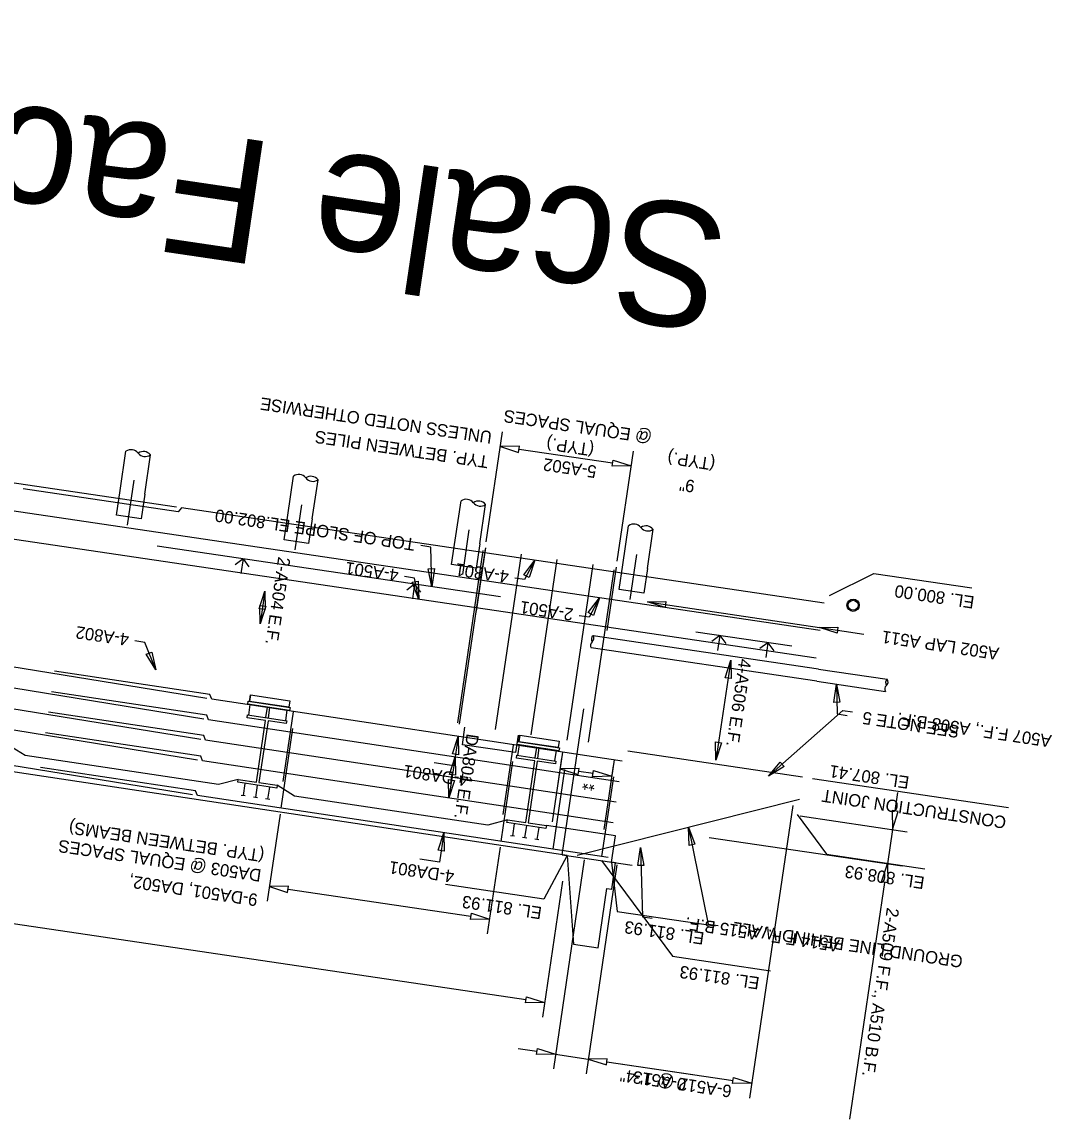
# Model space of a CAD drawing. Extents: x 1468952 to 1469875, y 573916 to 574139.
# Drawn here: x 1469049.93 to 1469091.48, y 574051.68 to 574095.95 of the extents above; entities that cross this region are included whole.
import ezdxf

# ---------------------------------------------------------------- set-up
doc = ezdxf.new("R2010")
doc.units = 0
for name, color, linetype in [('BR_P_Beam_Object', 7, 'Continuous'), ('BR_P_Beam_Stl_Det', 7, 'Continuous'), ('BR_P_Gen_Centerline', 7, 'Continuous'), ('BR_P_Gen_Phase_Construction', 7, 'Continuous'), ('BR_P_Sub_Centerline', 7, 'Continuous'), ('BR_P_Sub_Deep_Centerline', 7, 'Continuous'), ('BR_P_Sub_Foot_Centerline', 7, 'Continuous'), ('BR_P_Sub_Text', 7, 'Continuous'), ('BR_X_SV_Beam_Seat', 7, 'Continuous'), ('Default', 7, 'Continuous'), ('GE_P_CL_50', 7, 'Continuous'), ('GK_Cells', 7, 'Continuous'), ('PF_X_Ground_Line', 7, 'Continuous'), ('PV_X_EOP', 7, 'Continuous'), ('SV_X_Text_Elevation', 7, 'Continuous'), ('UT_X_Water', 7, 'Continuous')]:
    doc.layers.add(name, color=color, linetype=linetype)

# ---------------------------------------------------------------- blocks, each defined once
blk = doc.blocks.new('arrowOhio')
at = {"layer": 'Default'}
blk.add_lwpolyline([(0.00381, 0.000635), (0.00381, -0.000635), (0, 0)], close=True, dxfattribs=at)

msp = doc.modelspace()

# ---------------------------------------------------------------- linework, layer by layer
at = {"layer": 'BR_P_Beam_Object'}
for p, q in [((1469082.065, 574069.842), (1469072.965, 574071.189)), ((1469081.992, 574069.347), (1469072.891, 574070.694)), ((1469072.33, 574062.337), (1469081.288, 574064.593))]:
    msp.add_line(p, q, dxfattribs=at)
for centre, start, end in [((1469073.04, 574070.799), 127.976, 215.1816), ((1469073.076, 574071.046), 127.976, 215.1816), ((1469072.817, 574071.085), 307.976, 35.1816)]:
    msp.add_arc(centre, 0.181, start, end, dxfattribs=at)
at = {"layer": 'BR_P_Beam_Stl_Det'}
for p, q in [((1469068.524, 574074.626), (1469067.494, 574067.667)), ((1469068.619, 574074.697), (1469067.57, 574067.614)), ((1469068.625, 574074.738), (1469068.247, 574072.182)), ((1469070.063, 574074.483), (1469069.014, 574067.4)), ((1469071.507, 574074.269), (1469070.458, 574067.186)), ((1469072.951, 574074.055), (1469071.903, 574066.972)), ((1469073.901, 574073.957), (1469073.522, 574071.401)), ((1469073.8, 574073.845), (1469072.77, 574066.886))]:
    msp.add_line(p, q, dxfattribs=at)
for points in [[(1469056.161, 574076.372), (1469030.427, 574080.182), (1469030.303, 574080.026), (1469024.038, 574080.953)], [(1469082.126, 574071.391), (1469046.506, 574076.665), (1469046.433, 574076.85), (1469043.3, 574077.314)], [(1469082.291, 574072.504), (1469056.359, 574076.343), (1469056.235, 574076.186), (1469049.97, 574077.114)], [(1469081.962, 574070.278), (1469046.341, 574075.552), (1469046.268, 574075.738), (1469043.135, 574076.201)]]:
    msp.add_lwpolyline(points, dxfattribs=at)
at = {"layer": 'BR_P_Gen_Centerline'}
for p, q in [((1469082.065, 574069.842), (1469084.835, 574069.432)), ((1469081.992, 574069.347), (1469084.762, 574068.937))]:
    msp.add_line(p, q, dxfattribs=at)
for radius in [0.25, 0.2]:
    msp.add_circle((1469083.457, 574072.416), radius, dxfattribs=at)
for centre, start, end in [((1469084.91, 574069.041), 127.976, 215.1816), ((1469084.947, 574069.289), 127.976, 215.1816), ((1469084.687, 574069.327), 307.976, 35.1816)]:
    msp.add_arc(centre, 0.181, start, end, dxfattribs=at)
at = {"layer": 'BR_P_Gen_Phase_Construction'}
for p, q in [((1469053.887, 574077.046), (1469054.122, 574078.629)), ((1469054.877, 574076.9), (1469055.111, 574078.482)), ((1469060.647, 574076.045), (1469060.881, 574077.628)), ((1469061.636, 574075.899), (1469061.871, 574077.482)), ((1469067.407, 574075.045), (1469067.641, 574076.627)), ((1469068.396, 574074.898), (1469068.63, 574076.481)), ((1469074.166, 574074.044), (1469074.401, 574075.627)), ((1469075.155, 574073.897), (1469075.39, 574075.48))]:
    msp.add_line(p, q, dxfattribs=at)
for centre, start, end in [((1469054.331, 574078.332), 37.976, 125.1816), ((1469054.825, 574078.259), 37.976, 125.1816), ((1469054.902, 574078.779), 217.976, 305.1816), ((1469061.09, 574077.332), 37.976, 125.1816), ((1469061.585, 574077.258), 37.976, 125.1816), ((1469061.662, 574077.778), 217.976, 305.1816), ((1469067.85, 574076.331), 37.976, 125.1816), ((1469068.344, 574076.258), 37.976, 125.1816), ((1469068.421, 574076.777), 217.976, 305.1816), ((1469074.609, 574075.33), 37.976, 125.1816), ((1469075.104, 574075.257), 37.976, 125.1816), ((1469075.181, 574075.776), 217.976, 305.1816)]:
    msp.add_arc(centre, 0.362, start, end, dxfattribs=at)
at = {"layer": 'BR_P_Sub_Centerline'}
for p, q in [((1469053.741, 574076.057), (1469053.887, 574077.046)), ((1469054.877, 574076.9), (1469054.73, 574075.91)), ((1469054.73, 574075.91), (1469053.741, 574076.057)), ((1469060.501, 574075.056), (1469060.647, 574076.045)), ((1469061.636, 574075.899), (1469061.49, 574074.91)), ((1469061.49, 574074.91), (1469060.501, 574075.056)), ((1469067.26, 574074.055), (1469067.407, 574075.045)), ((1469068.396, 574074.898), (1469068.249, 574073.909)), ((1469068.249, 574073.909), (1469067.26, 574074.055)), ((1469074.02, 574073.055), (1469074.166, 574074.044)), ((1469075.155, 574073.897), (1469075.009, 574072.908)), ((1469075.009, 574072.908), (1469074.02, 574073.055))]:
    msp.add_line(p, q, dxfattribs=at)
at = {"layer": 'BR_P_Sub_Deep_Centerline'}
for q in [(1469072.594, 574068.231), (1469074.541, 574061.928)]:
    msp.add_line((1469071.723, 574062.345), q, dxfattribs=at)
at = {"layer": 'BR_P_Sub_Foot_Centerline'}
for p, q in [((1469059.073, 574067.986), (1469059.136, 574068.409)), ((1469059.77, 574067.883), (1469059.833, 574068.306)), ((1469059.869, 574067.868), (1469059.932, 574068.291)), ((1469060.566, 574067.765), (1469060.629, 574068.188)), ((1469069.936, 574066.358), (1469069.998, 574066.78)), ((1469070.633, 574066.255), (1469070.695, 574066.677)), ((1469070.732, 574066.24), (1469070.794, 574066.663)), ((1469071.429, 574066.137), (1469071.491, 574066.559))]:
    msp.add_line(p, q, dxfattribs=at)
at = {"layer": 'BR_P_Sub_Text'}
for p, q in [((1469057.382, 574068.654), (1469035.698, 574072.185)), ((1469057.26, 574067.826), (1469035.575, 574071.358)), ((1469057.137, 574066.999), (1469035.453, 574070.53)), ((1469057.015, 574066.171), (1469035.33, 574069.703)), ((1469057.506, 574068.81), (1469051.244, 574069.755)), ((1469057.384, 574067.983), (1469051.121, 574068.928)), ((1469057.58, 574068.624), (1469057.506, 574068.81)), ((1469074.146, 574066.124), (1469057.58, 574068.624)), ((1469056.807, 574064.767), (1469035.123, 574068.299)), ((1469057.261, 574067.155), (1469050.999, 574068.1)), ((1469057.457, 574067.797), (1469057.384, 574067.983)), ((1469074.023, 574065.297), (1469057.457, 574067.797)), ((1469060.87, 574068.11), (1469060.455, 574065.302)), ((1469057.139, 574066.328), (1469050.876, 574067.273)), ((1469060.38, 574064.229), (1469060.856, 574067.444)), ((1469057.335, 574066.969), (1469057.261, 574067.155)), ((1469073.901, 574064.469), (1469057.335, 574066.969)), ((1469069.744, 574066.776), (1469069.329, 574063.968)), ((1469071.733, 574066.482), (1469071.317, 574063.674)), ((1469057.212, 574066.142), (1469057.139, 574066.328)), ((1469073.778, 574063.642), (1469057.212, 574066.142)), ((1469069.253, 574062.89), (1469069.729, 574066.105)), ((1469073.817, 574066.181), (1469073.402, 574063.373)), ((1469056.931, 574064.924), (1469050.669, 574065.869)), ((1469071.356, 574062.572), (1469071.832, 574065.787)), ((1469073.323, 574062.275), (1469073.799, 574065.49)), ((1469057.005, 574064.738), (1469056.931, 574064.924)), ((1469073.571, 574062.238), (1469057.005, 574064.738))]:
    msp.add_line(p, q, dxfattribs=at)
at = {"layer": 'BR_X_SV_Beam_Seat'}
for p, q in [((1469069.23, 574072.753), (1469055.381, 574074.803)), ((1469058.844, 574074.29), (1469058.522, 574074.052)), ((1469058.844, 574074.29), (1469058.756, 574073.697)), ((1469058.844, 574074.29), (1469059.082, 574073.969)), ((1469065.768, 574073.265), (1469065.447, 574073.027)), ((1469065.768, 574073.265), (1469065.68, 574072.672)), ((1469065.768, 574073.265), (1469066.006, 574072.944)), ((1469080.988, 574070.759), (1469077.107, 574071.334)), ((1469078.078, 574071.19), (1469077.756, 574070.952)), ((1469078.078, 574071.19), (1469077.99, 574070.597)), ((1469078.078, 574071.19), (1469078.316, 574070.869)), ((1469080.018, 574070.903), (1469079.697, 574070.665)), ((1469080.018, 574070.903), (1469079.93, 574070.309)), ((1469080.018, 574070.903), (1469080.256, 574070.582)), ((1469081.815, 574065.421), (1469089.729, 574064.249))]:
    msp.add_line(p, q, dxfattribs=at)
msp.add_lwpolyline([(1469069.941, 574067.179), (1469069.836, 574066.468), (1469067.692, 574066.785), (1469067.798, 574067.496)], dxfattribs=at)
at = {"layer": 'GE_P_CL_50'}
for p, q in [((1469059.145, 574068.797), (1469059.107, 574068.539)), ((1469059.039, 574068.423), (1469059.057, 574068.547)), ((1469060.726, 574068.173), (1469059.039, 574068.423)), ((1469059.057, 574068.547), (1469060.744, 574068.297)), ((1469060.733, 574068.562), (1469060.694, 574068.304)), ((1469060.744, 574068.297), (1469060.726, 574068.173)), ((1469069.901, 574066.795), (1469069.92, 574066.918)), ((1469069.92, 574066.918), (1469071.606, 574066.669)), ((1469070.007, 574067.169), (1469069.969, 574066.911)), ((1469071.595, 574066.934), (1469071.557, 574066.676)), ((1469071.588, 574066.545), (1469069.901, 574066.795)), ((1469071.606, 574066.669), (1469071.588, 574066.545))]:
    msp.add_line(p, q, dxfattribs=at)
for points in [[(1469060.733, 574068.562), (1469060.694, 574068.304), (1469059.107, 574068.539), (1469059.145, 574068.797)], [(1469071.595, 574066.934), (1469071.557, 574066.676), (1469069.969, 574066.911), (1469070.007, 574067.169)]]:
    msp.add_lwpolyline(points, close=True, dxfattribs=at)
at = {"layer": 'GK_Cells'}
for p, q in [((1469059.015, 574067.879), (1469059.032, 574067.992)), ((1469059.753, 574067.77), (1469059.015, 574067.879)), ((1469059.032, 574067.992), (1469060.607, 574067.759)), ((1469059.384, 574065.276), (1469059.753, 574067.77)), ((1469059.853, 574067.755), (1469059.483, 574065.261)), ((1469060.591, 574067.646), (1469059.853, 574067.755)), ((1469060.607, 574067.759), (1469060.591, 574067.646)), ((1469069.878, 574066.251), (1469069.895, 574066.364)), ((1469070.616, 574066.141), (1469069.878, 574066.251)), ((1469069.895, 574066.364), (1469071.47, 574066.131)), ((1469070.247, 574063.648), (1469070.616, 574066.141)), ((1469070.715, 574066.127), (1469070.346, 574063.633)), ((1469071.453, 574066.018), (1469070.715, 574066.127)), ((1469071.47, 574066.131), (1469071.453, 574066.018)), ((1469058.629, 574065.272), (1469058.646, 574065.385)), ((1469060.205, 574065.039), (1469058.629, 574065.272)), ((1469058.646, 574065.385), (1469059.384, 574065.276)), ((1469058.922, 574065.229), (1469058.849, 574064.734)), ((1469059.417, 574065.155), (1469059.344, 574064.661)), ((1469059.483, 574065.261), (1469060.221, 574065.152)), ((1469059.912, 574065.082), (1469059.838, 574064.588)), ((1469060.221, 574065.152), (1469060.205, 574065.039)), ((1469058.932, 574064.722), (1469058.767, 574064.746)), ((1469059.426, 574064.649), (1469059.261, 574064.673)), ((1469059.921, 574064.575), (1469059.756, 574064.6)), ((1469069.492, 574063.644), (1469069.509, 574063.757)), ((1469069.509, 574063.757), (1469070.247, 574063.648)), ((1469071.067, 574063.411), (1469069.492, 574063.644)), ((1469069.785, 574063.6), (1469069.712, 574063.106)), ((1469070.279, 574063.527), (1469070.206, 574063.033)), ((1469070.346, 574063.633), (1469071.084, 574063.524)), ((1469070.774, 574063.454), (1469070.701, 574062.959)), ((1469071.084, 574063.524), (1469071.067, 574063.411)), ((1469069.794, 574063.094), (1469069.629, 574063.118)), ((1469070.289, 574063.02), (1469070.124, 574063.045)), ((1469070.783, 574062.947), (1469070.618, 574062.972))]:
    msp.add_line(p, q, dxfattribs=at)
at = {"layer": 'PF_X_Ground_Line'}
for p, q in [((1469071.925, 574062.316), (1469040.98, 574066.988)), ((1469073.868, 574063.112), (1469071.084, 574063.524)), ((1469073.711, 574062.048), (1469073.868, 574063.112)), ((1469071.925, 574062.316), (1469072.173, 574058.741)), ((1469071.925, 574062.316), (1469071.925, 574062.316)), ((1469071.925, 574062.316), (1469071.925, 574062.316)), ((1469073.876, 574062.027), (1469073.711, 574062.051)), ((1469073.718, 574060.955), (1469073.876, 574062.027)), ((1469073.165, 574058.594), (1469073.519, 574060.984)), ((1469073.519, 574060.984), (1469073.718, 574060.955)), ((1469072.173, 574058.741), (1469073.165, 574058.594))]:
    msp.add_line(p, q, dxfattribs=at)
for points in [[(1469058.646, 574065.385), (1469057.857, 574065.177), (1469050.054, 574066.355), (1469049.36, 574066.79)], [(1469069.509, 574063.757), (1469068.718, 574063.537), (1469060.915, 574064.715), (1469060.221, 574065.152)]]:
    msp.add_lwpolyline(points, dxfattribs=at)
at = {"layer": 'PV_X_EOP'}
msp.add_line((1469081.42, 574065.479), (1469074.373, 574066.522), dxfattribs=at)
at = {"layer": 'SV_X_Text_Elevation'}
for p, q in [((1469068.66, 574074.975), (1469069.317, 574079.412)), ((1469073.753, 574078.149), (1469069.981, 574078.707)), ((1469073.936, 574074.194), (1469074.593, 574078.631)), ((1469066.416, 574074.762), (1469066.021, 574074.821)), ((1469066.461, 574073.163), (1469066.416, 574074.762)), ((1469070.622, 574074.232), (1469070.203, 574073.458)), ((1469065.756, 574073.513), (1469065.36, 574073.572)), ((1469065.933, 574072.651), (1469065.756, 574073.513)), ((1469070.203, 574073.458), (1469069.807, 574073.516)), ((1469082.505, 574072.809), (1469084.293, 574073.704)), ((1469084.293, 574073.704), (1469088.25, 574073.118)), ((1469059.729, 574072.98), (1469059.535, 574071.671)), ((1469073.221, 574072.709), (1469072.802, 574071.936)), ((1469075.166, 574072.548), (1469082.103, 574071.521)), ((1469072.802, 574071.936), (1469072.407, 574071.994)), ((1469082.103, 574071.521), (1469083.101, 574071.373)), ((1469082.103, 574071.521), (1469082.103, 574071.521)), ((1469083.101, 574071.373), (1469083.892, 574071.256)), ((1469054.879, 574070.92), (1469054.484, 574070.979)), ((1469055.321, 574069.804), (1469054.879, 574070.92)), ((1469070.259, 574056.497), (1468978.025, 574070.152)), ((1469078.518, 574070.198), (1469077.921, 574066.166)), ((1469082.784, 574069.23), (1469082.817, 574068.03)), ((1469080.043, 574065.514), (1469083.035, 574068.169)), ((1469083.035, 574068.169), (1469083.431, 574068.11)), ((1469082.817, 574068.03), (1469083.212, 574067.972)), ((1469067.52, 574067.124), (1469067.344, 574065.937)), ((1469067.344, 574065.937), (1469066.552, 574066.054)), ((1469067.397, 574066.297), (1469067.152, 574064.642)), ((1469071.698, 574066.244), (1469071.547, 574065.228)), ((1469073.782, 574065.943), (1469073.631, 574064.919)), ((1469072.967, 574065.624), (1469072.387, 574065.71)), ((1469085.154, 574064.115), (1469085.265, 574064.867)), ((1469081.024, 574064.332), (1469079.277, 574052.533)), ((1469060.345, 574063.991), (1469059.823, 574060.47)), ((1469081.197, 574063.976), (1469082.389, 574062.37)), ((1469081.323, 574063.914), (1469085.636, 574063.276)), ((1469076.809, 574063.465), (1469077.612, 574059.546)), ((1469085.043, 574063.364), (1469084.838, 574061.983)), ((1469066.944, 574063.238), (1469066.768, 574062.051)), ((1469077.653, 574063.047), (1469085.432, 574061.895)), ((1469069.218, 574062.652), (1469068.7, 574059.155)), ((1469074.877, 574062.641), (1469074.955, 574059.842)), ((1469066.768, 574062.051), (1469065.977, 574062.168)), ((1469071.925, 574062.316), (1469070.973, 574060.557)), ((1469072.612, 574062.14), (1469071.363, 574053.705)), ((1469073.308, 574062.111), (1469076.168, 574058.256)), ((1469073.711, 574062.051), (1469073.941, 574060.064)), ((1469082.389, 574062.37), (1469086.346, 574061.784)), ((1469073.931, 574061.944), (1469072.682, 574053.51)), ((1469073.931, 574061.944), (1469072.682, 574053.51)), ((1469070.973, 574060.557), (1469067.017, 574061.142)), ((1469071.737, 574061.289), (1469070.923, 574055.792)), ((1469084.727, 574061.231), (1469083.314, 574051.684)), ((1469068.037, 574059.86), (1469060.663, 574060.952)), ((1469073.941, 574060.064), (1469077.897, 574059.478)), ((1469074.955, 574059.842), (1469075.35, 574059.784)), ((1469077.612, 574059.546), (1469078.008, 574059.488)), ((1469076.168, 574058.256), (1469080.125, 574057.671)), ((1469070.699, 574054.41), (1469069.948, 574054.521)), ((1469071.451, 574054.299), (1469072.77, 574054.103)), ((1469073.522, 574053.992), (1469078.613, 574053.238)), ((1469073.522, 574053.992), (1469076.997, 574053.478))]:
    msp.add_line(p, q, dxfattribs=at)
for points in [[(1469069.962, 574078.582), (1469069.999, 574078.832), (1469069.229, 574078.818)], [(1469073.734, 574078.023), (1469073.772, 574078.274), (1469074.505, 574078.037)], [(1469072.368, 574065.585), (1469072.405, 574065.835), (1469071.635, 574065.821)], [(1469072.948, 574065.499), (1469072.985, 574065.749), (1469073.718, 574065.513)], [(1469085.279, 574064.097), (1469085.029, 574064.134), (1469085.043, 574063.364)], [(1469084.852, 574061.213), (1469084.602, 574061.25), (1469084.838, 574061.983)], [(1469060.645, 574060.827), (1469060.682, 574061.077), (1469059.911, 574061.063)], [(1469068.018, 574059.735), (1469068.055, 574059.986), (1469068.788, 574059.749)], [(1469070.241, 574056.372), (1469070.278, 574056.622), (1469071.011, 574056.386)], [(1469070.681, 574054.285), (1469070.718, 574054.535), (1469071.451, 574054.299)], [(1469073.503, 574053.867), (1469073.541, 574054.117), (1469072.77, 574054.103)], [(1469073.503, 574053.867), (1469073.541, 574054.117), (1469072.77, 574054.103)], [(1469078.595, 574053.113), (1469078.632, 574053.364), (1469079.365, 574053.127)]]:
    msp.add_lwpolyline(points, close=True, dxfattribs=at)
at = {"layer": 'UT_X_Water'}
for p, q in [((1469054.187, 574075.654), (1469054.455, 574077.467)), ((1469060.946, 574074.653), (1469061.215, 574076.467)), ((1469067.706, 574073.652), (1469067.974, 574075.466)), ((1469074.466, 574072.652), (1469074.734, 574074.465))]:
    msp.add_line(p, q, dxfattribs=at)

# ---------------------------------------------------------------- block references
at = {"layer": 'SV_X_Text_Elevation'}
for p, xscale, yscale, rotation in [((1469070.622, 574074.232), 191.49568, 191.49568000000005, -118.42123067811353), ((1469066.461, 574073.163), 191.49568, 191.49568, 91.57876932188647), ((1469065.933, 574072.651), 191.49568000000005, 191.49568, 101.57876932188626), ((1469059.729, 574072.98), 191.49568000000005, 191.49568, -98.42123067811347), ((1469073.221, 574072.709), 191.49568, 191.49568000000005, -118.42123067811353), ((1469075.166, 574072.548), 191.49568000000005, 191.49568, -8.421230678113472), ((1469059.535, 574071.671), 191.49568000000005, 191.49568, 81.57876932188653), ((1469082.103, 574071.521), 191.49568000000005, 191.49568, -8.421230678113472), ((1469055.321, 574069.804), 191.49568000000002, 191.49568000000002, 111.57876932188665), ((1469078.518, 574070.198), 191.49568000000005, 191.49568, -98.42123067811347), ((1469082.784, 574069.23), 191.49568000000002, 191.49568000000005, -88.42123067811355), ((1469067.52, 574067.124), 191.49568000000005, 191.49568, -98.42123067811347), ((1469077.921, 574066.166), 191.49568000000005, 191.49568, 81.57876932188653), ((1469067.397, 574066.297), 191.49568000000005, 191.49568, -98.42123067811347), ((1469080.043, 574065.514), 191.49568000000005, 191.49568, 41.57876932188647), ((1469067.152, 574064.642), 191.49568000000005, 191.49568, 81.57876932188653), ((1469076.809, 574063.465), 191.49568000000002, 191.49568000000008, -78.42123067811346), ((1469066.944, 574063.238), 191.49568000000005, 191.49568, -98.42123067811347), ((1469074.877, 574062.641), 191.49568, 191.49568000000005, -88.42123067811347)]:
    msp.add_blockref('arrowOhio', p, dxfattribs=dict(at, xscale=xscale, yscale=yscale, rotation=rotation))

# ---------------------------------------------------------------- texts
for s, height, rotation, p in [('Scale Factor = 48', 4.99999, 171.5788, (1469078.57, 574088.343)), ('UNLESS NOTED OTHERWISE', 0.5, 171.5788, (1469068.914, 574079.425)), (' @ EQUAL SPACES', 0.5, 171.5788, (1469075.553, 574079.398)), ('TYP. BETWEEN PILES', 0.5, 171.5788, (1469068.768, 574078.436)), ('(TYP.)', 0.5, 171.5788, (1469073.032, 574078.912)), ('5-A502', 0.5, 171.5788, (1469073.131, 574078.038)), ('(TYP.)', 0.5, 171.5788, (1469077.918, 574078.341)), ('9"', 0.5, 171.5788, (1469077.094, 574077.452)), ('TOP OF SLOPE EL.802.00', 0.5, 171.5788, (1469065.81, 574075.105)), ('2-A504 E.F.', 0.5, 261.5788, (1469060.267, 574074.39)), ('4-A501', 0.5, 171.5788, (1469065.149, 574073.856)), ('4-A801', 0.5, 171.5788, (1469069.596, 574073.8)), ('EL. 800.00', 0.5, 171.5788, (1469088.373, 574072.771)), ('2-A501', 0.5, 171.5788, (1469072.196, 574072.278)), ('4-A802', 0.5, 171.5788, (1469054.273, 574071.263)), ('A502 LAP A511', 0.5, 171.5788, (1469089.366, 574070.698)), ('4-A506 E.F.', 0.5, 261.5788, (1469078.859, 574070.279)), ('SEE NOTE 5', 0.5, 171.5788, (1469087.769, 574067.55)), ('A507 F.F., A508 B.F.', 0.5, 171.5788, (1469091.483, 574067.171)), ('DA801 E.F.', 0.5, 261.5788, (1469067.868, 574067.254)), ('4-DA801', 0.5, 171.5788, (1469067.968, 574065.596)), ('EL. 807.41', 0.5, 171.5788, (1469085.746, 574065.5)), ('**', 0.5, 171.5788, (1469073.089, 574065.404)), ('CONSTRUCTION JOINT', 0.5, 171.5788, (1469089.659, 574063.889)), ('(TYP. BETWEEN BEAMS)', 0.5, 171.5788, (1469059.726, 574062.54)), ('DA503 @ EQUAL SPACES', 0.5, 171.5788, (1469059.608, 574061.749)), ('4-DA801', 0.5, 171.5788, (1469067.392, 574061.71)), ('9-DA501, DA502,', 0.5, 171.5788, (1469059.462, 574060.76)), ('EL. 808.93', 0.5, 171.5788, (1469086.363, 574061.452)), ('EL. 811.93', 0.5, 171.5788, (1469070.926, 574060.234)), ('2-A509 F.F., A510 B.F.', 0.5, 261.5788, (1469084.823, 574060.235)), ('A514 F.F., A515 B.F.', 0.5, 171.5788, (1469082.932, 574058.914)), ('EL. 811.93', 0.5, 171.5788, (1469077.477, 574059.211)), ('GROUND LINE BEHIND WALL', 0.5, 171.5788, (1469087.908, 574058.275)), ('EL. 811.93', 0.5, 171.5788, (1469079.704, 574057.403)), ('6-A512 @ 1\'-4"', 0.5, 171.5788, (1469078.584, 574053.04)), ('0-A513', 0.5, 171.5788, (1469076.751, 574053.312))]:
    msp.add_text(s, height=height, rotation=rotation, dxfattribs=at).set_placement(p)

doc.saveas('drawing.dxf')
